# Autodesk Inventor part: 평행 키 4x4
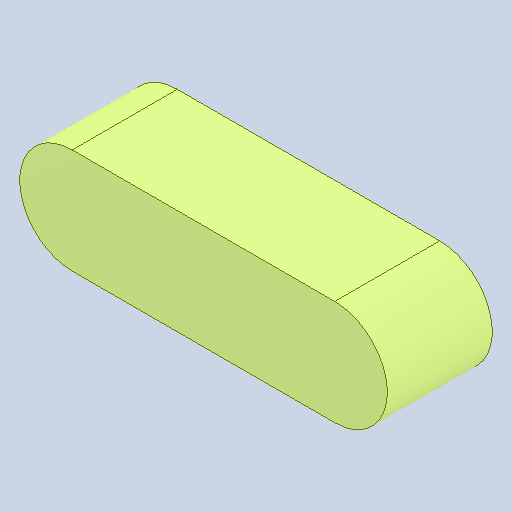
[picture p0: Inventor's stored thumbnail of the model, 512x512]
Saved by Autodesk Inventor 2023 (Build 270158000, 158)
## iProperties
Created: 2025-04
Part Number: 평행 키 4x4
Material: 강철, 연강
Document SubType Name: Modeling
Designer: Admin
Density: 7.86 g/cm^3
Appearance: 기본값
Author: jhkim
Revision Number: 1
Sending System: Autodesk Inventor 2026
Preprocessor: ST-DEVELOPER v20.1
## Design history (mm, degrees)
feature "솔리드1"
node "솔리드2"
